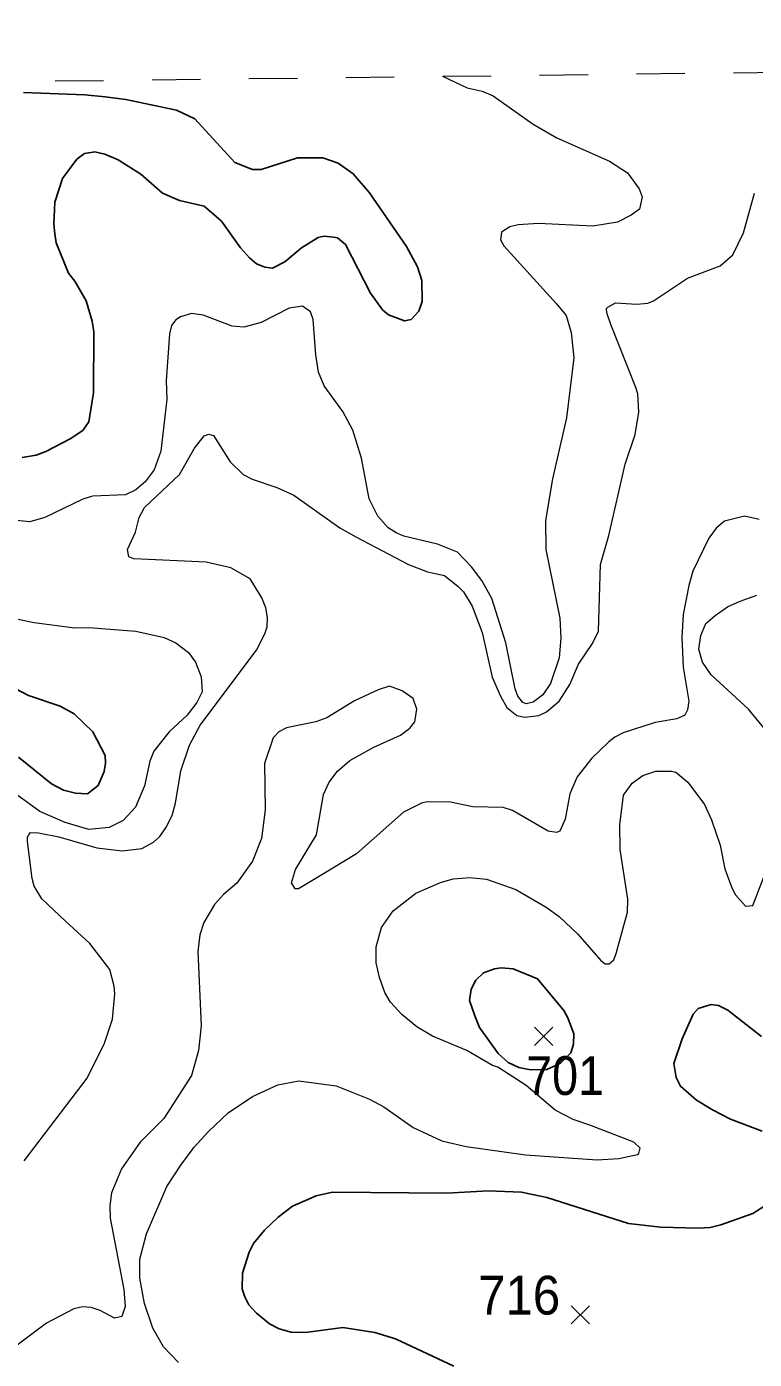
# Model space of a CAD drawing. Extents: x 294.2 to 320.3, y 7482.7 to 7510.7.
# Drawn here: x 310.642 to 312.145, y 7507.992 to 7510.744 of the extents above; entities that cross this region are included whole.
import ezdxf
from ezdxf.enums import TextEntityAlignment as Align

# ---------------------------------------------------------------- set-up
doc = ezdxf.new("R2010")
doc.units = 0
doc.header["$LTSCALE"] = 0.032
doc.linetypes.add('SHORT_DASHED', pattern=[2.7, 1.5, -1.2])
for name, color, linetype, lineweight in [('1', 7, 'Continuous', 25), ('2', 7, 'Continuous', 13), ('21', 7, 'Continuous', 25), ('22', 7, 'SHORT_DASHED', 13)]:
    doc.layers.add(name, color=color, linetype=linetype, lineweight=lineweight)
doc.layers.add('61', color=7, linetype='Continuous')

msp = doc.modelspace()

# ---------------------------------------------------------------- linework, layer by layer
at = {"layer": '1'}
for points in [[(310.6329, 7509.8545), (310.6623, 7509.8593), (310.6817, 7509.8669), (310.7322, 7509.8927), (310.7583, 7509.9099), (310.7711, 7509.9276), (310.7805, 7509.9879), (310.7809, 7510.1137), (310.7776, 7510.1358), (310.7653, 7510.1775), (310.7419, 7510.2183), (310.7286, 7510.235), (310.7037, 7510.2974), (310.7005, 7510.316), (310.6987, 7510.3362), (310.7009, 7510.3814), (310.7164, 7510.4303), (310.7458, 7510.4701), (310.7619, 7510.4819), (310.7835, 7510.4851), (310.8041, 7510.4803), (310.8312, 7510.4685), (310.8783, 7510.4395), (310.9227, 7510.4002), (310.9582, 7510.3846), (311.0092, 7510.3728), (311.0447, 7510.3421), (311.0841, 7510.2868), (311.1024, 7510.2664), (311.1168, 7510.254), (311.134, 7510.247), (311.1501, 7510.2454), (311.1751, 7510.2583), (311.21, 7510.2873), (311.2439, 7510.3083), (311.2566, 7510.3115), (311.2755, 7510.3093), (311.2838, 7510.3077), (311.3004, 7510.2943), (311.3519, 7510.1937), (311.3769, 7510.1593), (311.3897, 7510.1486), (311.4224, 7510.1362), (311.4363, 7510.1394), (311.4523, 7510.1561), (311.459, 7510.1765), (311.4579, 7510.2195), (311.449, 7510.248), (311.4263, 7510.2899), (311.3503, 7510.4007), (311.3165, 7510.44), (311.2854, 7510.462), (311.2538, 7510.4728), (311.2017, 7510.4728), (311.1268, 7510.4491), (311.1085, 7510.4491), (311.0719, 7510.4631), (310.9893, 7510.5534), (310.9516, 7510.5711), (310.8473, 7510.5932), (310.8046, 7510.5986), (310.7625, 7510.6029), (310.636, 7510.6077)], [(310.6254, 7509.2358), (310.6935, 7509.1807), (310.7185, 7509.1672), (310.7434, 7509.1613), (310.7678, 7509.1597), (310.79, 7509.1769), (310.8022, 7509.2059), (310.8055, 7509.2231), (310.8044, 7509.2387), (310.7789, 7509.2877), (310.7406, 7509.3248), (310.7117, 7509.341), (310.6462, 7509.3631), (310.563, 7509.4061)], [(312.1592, 7508.659), (312.0895, 7508.7132), (312.0706, 7508.7229), (312.0556, 7508.7251), (312.0285, 7508.7164), (312.0185, 7508.7052), (311.9957, 7508.6541), (311.9786, 7508.6029), (311.983, 7508.5744), (311.9919, 7508.5562), (312.0252, 7508.5277), (312.0584, 7508.5078), (312.0956, 7508.4885), (312.1605, 7508.4638)], [(312.2309, 7508.3503), (312.1417, 7508.2933), (312.0751, 7508.2701), (312.0535, 7508.2647), (312.0285, 7508.2631), (311.9509, 7508.2653), (311.8849, 7508.2729), (311.7162, 7508.3266), (311.6641, 7508.3374), (311.5954, 7508.3406), (311.5095, 7508.3357), (311.2737, 7508.3374), (311.2399, 7508.3299), (311.1913, 7508.3083), (311.1614, 7508.2857), (311.1336, 7508.2588), (311.1109, 7508.2319), (311.1015, 7508.2136), (311.0882, 7508.1701), (311.0876, 7508.1378), (311.0926, 7508.1212), (311.101, 7508.105)], [(311.101, 7508.105), (311.117, 7508.0878), (311.1436, 7508.0658), (311.1636, 7508.0555), (311.1885, 7508.0485), (311.2179, 7508.0475), (311.295, 7508.0583)], [(311.295, 7508.0583), (311.3609, 7508.048), (311.4036, 7508.0346), (311.524, 7507.9786)]]:
    msp.add_lwpolyline(points, dxfattribs=at)
msp.add_lwpolyline([(311.7595, 7508.6977), (311.7716, 7508.6642), (311.7715, 7508.6431), (311.7654, 7508.625), (311.7443, 7508.6038), (311.7163, 7508.591), (311.6827, 7508.5904), (311.6585, 7508.595), (311.6366, 7508.6055), (311.6154, 7508.6237), (311.5772, 7508.6773), (311.5674, 7508.7015), (311.5568, 7508.7332), (311.5598, 7508.7566), (311.5696, 7508.7755), (311.5855, 7508.7906), (311.6085, 7508.7989), (311.6221, 7508.8004), (311.647, 7508.7989), (311.6969, 7508.7777), (311.7511, 7508.7128)], close=True, dxfattribs=at)
at = {"layer": '2'}
for points in [[(311.5006, 7510.6413), (311.552, 7510.6174), (311.5826, 7510.6104), (311.6056, 7510.6008), (311.6879, 7510.5427), (311.7371, 7510.514), (311.8456, 7510.466), (311.8827, 7510.4418), (311.9069, 7510.4092), (311.9127, 7510.3926), (311.9076, 7510.3671), (311.8903, 7510.3543), (311.8623, 7510.3403), (311.8112, 7510.332), (311.6988, 7510.3371), (311.6567, 7510.3345), (311.64, 7510.3307), (311.6228, 7510.3192), (311.6203, 7510.3039), (311.6273, 7510.2911), (311.7358, 7510.1717), (311.7562, 7510.1474), (311.7664, 7510.1124), (311.7722, 7510.06), (311.7569, 7509.9361), (311.7281, 7509.8103), (311.7135, 7509.7242), (311.7141, 7509.6642), (311.7428, 7509.5224), (311.7454, 7509.4815), (311.7416, 7509.4407), (311.7237, 7509.3877), (311.7081, 7509.3644), (311.688, 7509.3488), (311.6737, 7509.3455), (311.6668, 7509.3483), (311.6564, 7509.3616), (311.6509, 7509.3768), (311.6318, 7509.4713), (311.6024, 7509.5633), (311.582, 7509.6003), (311.5609, 7509.6284), (311.5315, 7509.659), (311.4907, 7509.675), (311.421, 7509.6916), (311.4051, 7509.6986), (311.3885, 7509.7088), (311.3674, 7509.7331), (311.3495, 7509.7689), (311.3335, 7509.8531), (311.3157, 7509.9106), (311.2953, 7509.9495), (311.2569, 7510.0019), (311.2448, 7510.0306), (311.2391, 7510.0664), (311.2339, 7510.1392), (311.2282, 7510.1551), (311.2116, 7510.1666), (311.1842, 7510.1628), (311.1267, 7510.1328), (311.091, 7510.1232), (311.0667, 7510.1251), (311.0067, 7510.1481), (310.9824, 7510.1513), (310.96, 7510.1449), (310.9505, 7510.1385), (310.9416, 7510.127), (310.9371, 7510.1098), (310.9307, 7510.0128), (310.932, 7509.9745), (310.9192, 7509.8672), (310.9058, 7509.8289), (310.8873, 7509.8039), (310.8675, 7509.7873), (310.8464, 7509.7772), (310.7781, 7509.7746), (310.7583, 7509.7682), (310.6798, 7509.7305), (310.6491, 7509.7216), (310.6147, 7509.7248)], [(310.9786, 7509.2606), (311.0009, 7509.3015), (311.1171, 7509.4566), (311.1344, 7509.4905), (311.1388, 7509.5045), (311.1395, 7509.5237), (311.1363, 7509.5441), (311.128, 7509.5646), (311.1037, 7509.6035), (311.0642, 7509.6265), (311.0131, 7509.638), (310.8636, 7509.645), (310.8534, 7509.6495), (310.8509, 7509.6641), (310.8669, 7509.6999), (310.8745, 7509.7306), (310.8854, 7509.751), (310.9581, 7509.8193), (310.9888, 7509.8736), (311.0092, 7509.8991), (311.0182, 7509.9023), (311.0284, 7509.8997), (311.0622, 7509.8455), (311.0896, 7509.8193), (311.1076, 7509.8097), (311.1586, 7509.7925), (311.1937, 7509.7765), (311.2889, 7509.7088), (311.3221, 7509.6903), (311.4306, 7509.6335), (311.4702, 7509.6182), (311.5047, 7509.6105), (311.5334, 7509.5882), (311.5443, 7509.5767), (311.5622, 7509.5473), (311.5826, 7509.493), (311.6036, 7509.4004), (311.6203, 7509.3615), (311.6336, 7509.3379), (311.6541, 7509.3219), (311.6707, 7509.3181), (311.6994, 7509.3219), (311.7154, 7509.3289), (311.7416, 7509.3513), (311.7639, 7509.3858), (311.7818, 7509.4279), (311.8105, 7509.4701), (311.8226, 7509.4956), (311.8271, 7509.6335), (311.8443, 7509.6935), (311.8782, 7509.8404), (311.8986, 7509.9017), (311.9063, 7509.9476), (311.9037, 7509.9859), (311.8999, 7509.9987), (311.8482, 7510.129), (311.8399, 7510.1532), (311.8392, 7510.1621), (311.8418, 7510.1647), (311.8578, 7510.1736), (311.9018, 7510.1705), (311.9248, 7510.173), (311.9363, 7510.1774), (312.0065, 7510.2247), (312.0742, 7510.2502), (312.1004, 7510.2726), (312.1221, 7510.318), (312.1451, 7510.3997)], [(312.1547, 7509.7261), (312.124, 7509.7331), (312.0831, 7509.7228), (312.0659, 7509.7082), (312.0506, 7509.6877), (312.0174, 7509.6194), (312.0091, 7509.5901), (311.9976, 7509.5301), (311.995, 7509.4828), (311.9976, 7509.4215), (312.0091, 7509.3513), (312.0065, 7509.3334), (312.0008, 7509.3225), (311.9848, 7509.3149), (311.9401, 7509.3072), (311.8737, 7509.2855), (311.8565, 7509.2772), (311.8444, 7509.267), (311.8092, 7509.2332), (311.7786, 7509.1948), (311.7639, 7509.1598), (311.7543, 7509.1074), (311.7428, 7509.0825), (311.7358, 7509.0799), (311.7192, 7509.0831), (311.6452, 7509.1252), (311.626, 7509.1316), (311.5634, 7509.1329)], [(312.17, 7509.2887), (312.1323, 7509.3347), (312.0557, 7509.4056), (312.0378, 7509.4317), (312.0302, 7509.4586), (312.034, 7509.4867), (312.0442, 7509.5115), (312.064, 7509.5281), (312.0889, 7509.546), (312.1151, 7509.5575), (312.1495, 7509.5703)], [(310.624, 7509.5205), (310.6581, 7509.5134)], [(310.6581, 7509.5134), (310.7417, 7509.5026), (310.7705, 7509.5032), (310.8675, 7509.4956), (310.9262, 7509.4828), (310.9505, 7509.4713), (310.9767, 7509.4515)], [(310.9767, 7509.4515), (310.9913, 7509.4317), (311.0028, 7509.4011), (311.0048, 7509.3705), (310.9939, 7509.3487), (310.9735, 7509.3226), (310.9364, 7509.2881), (310.9051, 7509.2479), (310.8968, 7509.2274), (310.886, 7509.1764), (310.8669, 7509.1323), (310.8419, 7509.1048), (310.8126, 7509.0902), (310.7705, 7509.0863), (310.7219, 7509.1004), (310.6696, 7509.1234), (310.5559, 7509.2051)], [(311.2519, 7508.9924), (311.2033, 7508.9637), (311.197, 7508.9637), (311.1892, 7508.9759), (311.1976, 7509.004), (311.241, 7509.0755), (311.2551, 7509.1585), (311.2671, 7509.184), (311.2838, 7509.207), (311.3093, 7509.2287), (311.3591, 7509.2562), (311.414, 7509.281), (311.4332, 7509.2957), (311.444, 7509.3085), (311.4479, 7509.3347), (311.4402, 7509.357), (311.4179, 7509.3724), (311.3911, 7509.3819), (311.3681, 7509.3749), (311.3195, 7509.3519), (311.2621, 7509.3168), (311.2391, 7509.3085), (311.1791, 7509.2963), (311.1631, 7509.2881), (311.1516, 7509.2753), (311.1337, 7509.2223), (311.135, 7509.1266), (311.1274, 7509.0678), (311.1088, 7509.0206), (311.0763, 7508.9758), (311.0488, 7508.9522), (311.0303, 7508.9311), (311.0079, 7508.8942), (310.9997, 7508.8686), (310.9958, 7508.8341), (311.0028, 7508.6809), (310.9971, 7508.6298), (310.9824, 7508.5781), (310.9256, 7508.4893), (310.877, 7508.4408), (310.8381, 7508.3859), (310.8177, 7508.3361), (310.8138, 7508.3093), (310.8145, 7508.2838), (310.8432, 7508.1369), (310.8457, 7508.1012), (310.8388, 7508.0807), (310.8241, 7508.0775), (310.7941, 7508.0935), (310.7756, 7508.0992), (310.7577, 7508.1005), (310.7398, 7508.0967), (310.6836, 7508.0673), (310.5955, 7508.0009)], [(310.9045, 7509.0601), (310.9173, 7509.0716), (310.93, 7509.0895), (310.9428, 7509.1151), (310.9499, 7509.1406), (310.9607, 7509.2076), (310.9786, 7509.2606)], [(311.0584, 7508.5015), (311.1088, 7508.5353), (311.1612, 7508.5589), (311.2046, 7508.5672), (311.2812, 7508.557), (311.3502, 7508.5296), (311.3795, 7508.5136), (311.4402, 7508.4708), (311.4996, 7508.4433), (311.5494, 7508.4318), (311.6721, 7508.4147), (311.8201, 7508.4044), (311.8648, 7508.407), (311.9031, 7508.4152), (311.9063, 7508.4172), (311.9089, 7508.4287), (311.8955, 7508.4408), (311.8048, 7508.4759), (311.7703, 7508.4874), (311.7335, 7508.5067), (311.6738, 7508.5577), (311.6152, 7508.5955), (311.6037, 7508.5991), (311.5513, 7508.6298), (311.4804, 7508.6598), (311.4479, 7508.679), (311.4172, 7508.7045), (311.3936, 7508.73), (311.3815, 7508.7499), (311.3706, 7508.7805), (311.3636, 7508.8111), (311.3636, 7508.8437), (311.3751, 7508.8839), (311.3993, 7508.9184), (311.446, 7508.9548), (311.497, 7508.9771), (311.5226, 7508.9842), (311.5571, 7508.9873), (311.5915, 7508.9835), (311.6522, 7508.9625), (311.7147, 7508.926), (311.7416, 7508.9069), (311.7805, 7508.8705), (311.8277, 7508.8156), (311.8367, 7508.8086), (311.845, 7508.8086), (311.8546, 7508.8175), (311.8591, 7508.8303), (311.8826, 7508.9159), (311.8833, 7508.9427), (311.8673, 7509.0448), (311.8667, 7509.0959), (311.8744, 7509.1572), (311.8922, 7509.1821), (311.9146, 7509.1974), (311.9414, 7509.2064), (311.9733, 7509.207), (311.9823, 7509.2044), (312.0072, 7509.184), (312.0417, 7509.138), (312.0563, 7509.1061), (312.0742, 7509.0538), (312.0838, 7509.0052), (312.0978, 7508.9657), (312.1055, 7508.9516), (312.1266, 7508.928), (312.1412, 7508.9293), (312.2064, 7509.0972)], [(311.5634, 7509.1329), (311.5175, 7509.1425), (311.4689, 7509.1431), (311.4575, 7509.1406), (311.4204, 7509.1221), (311.3234, 7509.0359), (311.2519, 7508.9924)], [(310.6376, 7508.4025), (310.7673, 7508.573), (310.803, 7508.6451), (310.8196, 7508.6949), (310.8247, 7508.7473), (310.8234, 7508.7626), (310.8138, 7508.7971), (310.773, 7508.8507), (310.7226, 7508.8973), (310.674, 7508.9433), (310.658, 7508.9695), (310.6536, 7508.9848), (310.644, 7509.0614), (310.644, 7509.0704), (310.6478, 7509.0767), (310.6504, 7509.0799), (310.667, 7509.0793), (310.7092, 7509.071), (310.7871, 7509.0486), (310.8394, 7509.0422), (310.8803, 7509.0467), (310.9045, 7509.0601)], [(310.8758, 7508.1995), (310.8898, 7508.2518), (310.932, 7508.3495), (310.9607, 7508.3936), (310.9882, 7508.4306), (311.0175, 7508.4631), (311.0584, 7508.5015)], [(310.9556, 7507.9856), (310.9249, 7508.0181), (310.9032, 7508.0571), (310.886, 7508.1075), (310.8758, 7508.1599), (310.8758, 7508.1995)]]:
    msp.add_lwpolyline(points, dxfattribs=at)
at = {"layer": '21'}
for p, q in [((311.6909, 7508.6779), (311.7284, 7508.6404)), ((311.7284, 7508.6779), (311.6909, 7508.6404)), ((311.7667, 7508.1032), (311.8042, 7508.0657)), ((311.8042, 7508.1032), (311.7667, 7508.0657))]:
    msp.add_line(p, q, dxfattribs=at)
at = {"layer": '22'}
msp.add_lwpolyline([(294.2515, 7510.4214), (307.9016, 7510.5978), (319.9762, 7510.7437)], dxfattribs=at)

# ---------------------------------------------------------------- texts
at = {"layer": '61'}
for s, width, p in [('701', 0.9, (311.7539, 7508.5382)), ('716', 0.95, (311.659, 7508.0849))]:
    msp.add_text(s, height=0.08, dxfattribs=dict(at, width=width)).set_placement(p, align=Align.CENTER)

doc.saveas('drawing.dxf')
